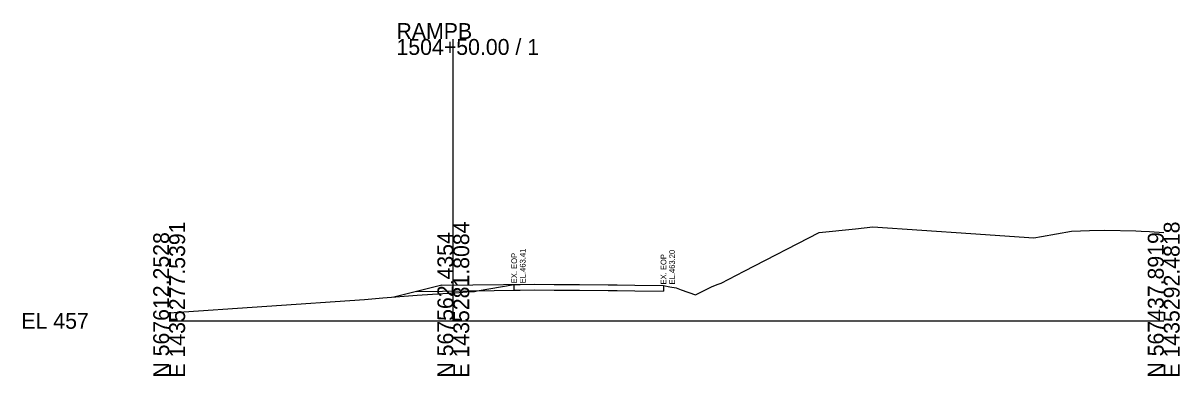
# Model space of a CAD drawing. Extents: x 1431908 to 1449087, y 567604 to 577825.
# Drawn here: x 1439484.4 to 1439688, y 576048.6 to 576110.7 of the extents above; entities that cross this region are included whole.
import ezdxf

# ---------------------------------------------------------------- set-up
doc = ezdxf.new("R2010")
doc.units = 0
for name, color, linetype in [('DESIGN - SHEET - Light Grid', 7, 'Continuous'), ('DESIGN - TYPICAL - Finished Grade and Subgrade', 7, 'Continuous'), ('SURVEY - GROUND - Existing Pavement Layer', 7, 'Continuous'), ('SURVEY - GROUND - Existing Pavement Text', 7, 'Continuous'), ('SURVEY - GROUND - Top of Ground', 7, 'Continuous')]:
    doc.layers.add(name, color=color, linetype=linetype)

msp = doc.modelspace()

# ---------------------------------------------------------------- linework, layer by layer
at = {"layer": 'DESIGN - SHEET - Light Grid'}
for p, q in [((1439560.12, 576058.33), (1439560.12, 576107.94)), ((1439510.12, 576058.33), (1439560.12, 576058.33)), ((1439560.12, 576058.33), (1439685.12, 576058.33))]:
    msp.add_line(p, q, dxfattribs=at)
at = {"layer": 'DESIGN - TYPICAL - Finished Grade and Subgrade'}
for p, q in [((1439558.12, 576064.63), (1439549.68, 576062.51)), ((1439558.12, 576064.63), (1439574.4, 576064.78)), ((1439571.87, 576064.75), (1439571.87, 576064.75))]:
    msp.add_line(p, q, dxfattribs=at)
at = {"layer": 'SURVEY - GROUND - Existing Pavement Layer'}
for p, q in [((1439570.83, 576063.74), (1439570.83, 576064.74)), ((1439597.11, 576064.53), (1439597.11, 576063.53)), ((1439553.65, 576063.51), (1439571.87, 576063.75)), ((1439570.83, 576063.74), (1439571.87, 576063.75)), ((1439571.87, 576063.75), (1439574.4, 576063.78)), ((1439574.4, 576063.78), (1439577.89, 576063.75)), ((1439577.89, 576063.75), (1439582.34, 576063.71)), ((1439582.34, 576063.71), (1439587.35, 576063.67)), ((1439587.35, 576063.67), (1439588.94, 576063.65)), ((1439588.94, 576063.65), (1439592.07, 576063.6)), ((1439592.07, 576063.6), (1439597.11, 576063.53))]:
    msp.add_line(p, q, dxfattribs=at)
at = {"layer": 'SURVEY - GROUND - Top of Ground'}
msp.add_lwpolyline([(1439510.12, 576059.74), (1439544.52, 576062.09), (1439547.74, 576062.36), (1439553.75, 576062.85), (1439560.12, 576063.25), (1439560.47, 576063.28), (1439562.49, 576063.41), (1439563.82, 576063.49), (1439564.31, 576063.58), (1439570.83, 576064.74), (1439571.87, 576064.75), (1439574.4, 576064.78), (1439577.89, 576064.75), (1439582.34, 576064.71), (1439587.35, 576064.67), (1439588.94, 576064.65), (1439592.07, 576064.6), (1439597.11, 576064.53), (1439598.22, 576064.32), (1439599.33, 576064.11), (1439600.22, 576063.78), (1439602.72, 576062.88), (1439603.68, 576063.36), (1439605.65, 576064.4), (1439606.7, 576064.76), (1439607.25, 576064.96), (1439611.27, 576067.05), (1439624.49, 576073.89), (1439630.88, 576074.55), (1439633.96, 576074.87), (1439651.18, 576073.69), (1439662.24, 576072.92), (1439663.62, 576073.16), (1439668.92, 576074.11), (1439672.06, 576074.21), (1439674.75, 576074.29), (1439680.2, 576074.16), (1439681.18, 576074.14), (1439682.64, 576074.03), (1439685.12, 576073.85)], dxfattribs=at)

# ---------------------------------------------------------------- texts
at = {"layer": 'DESIGN - SHEET - Light Grid'}
for s, p in [('RAMPB', (1439550.12, 576107.94)), ('1504+50.00 / 1', (1439550.12, 576105.14)), ('EL 457', (1439484.12, 576056.93))]:
    msp.add_text(s, height=2.8, dxfattribs=at).set_placement(p)
for s, p in [('E 1435277.5391', (1439512.92, 576048.33)), ('E 1435281.8084', (1439562.92, 576048.33)), ('E 1435292.4818', (1439687.92, 576048.33)), ('N 567612.2528', (1439510.12, 576048.33)), ('N 567562.4354', (1439560.12, 576048.33)), ('N 567437.8919', (1439685.12, 576048.33))]:
    msp.add_text(s, height=2.8, rotation=90, dxfattribs=at).set_placement(p)
at = {"layer": 'SURVEY - GROUND - Existing Pavement Text'}
for s, p in [('EL.463.41', (1439572.83, 576064.94)), ('EL.463.20', (1439599.11, 576064.73)), ('EX. EOP', (1439571.33, 576064.94)), ('EX. EOP', (1439597.61, 576064.73))]:
    msp.add_text(s, height=1, rotation=90, dxfattribs=at).set_placement(p)

doc.saveas('drawing.dxf')
